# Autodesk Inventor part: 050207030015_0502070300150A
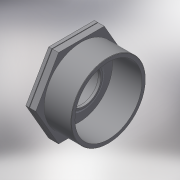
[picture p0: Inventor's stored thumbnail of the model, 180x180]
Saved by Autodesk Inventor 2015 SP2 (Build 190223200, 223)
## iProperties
Created: 2017-05
Part Number: 050207030015_0502070300150A
Material: Generic
Description: PLASSON REDUCING BUSHING 3"-1.1/2"
Document SubType Name: Modeling
Designer: KIM
Density: 1 g/cm^3
Appearance: Default
Author: KIM
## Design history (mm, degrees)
derived "050207.ipt"
feature "Solid1::050207.ipt"
tag "TaggingFeature1"
body "Solid1"
other parameters: "d1" = 87.884, "d5" = 32, "d8" = 0.48, "d12" = 0, "d15" = 48, "d19" = 0, "d30" = 9.6, "d31" = 4.8, "d33" = 44.845, "d34" = 79.0956, "d36" = 4.5, "d37" = 53.814, "d38" = 31.68, "d39" = 40.3605, "d40" = 3.2, "d41" = 0, "H_" = 48, "R_" = 87.884, "l_2" = 32, "Rp_" = 44.845
